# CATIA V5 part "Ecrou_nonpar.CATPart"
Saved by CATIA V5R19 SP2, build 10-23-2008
Part number: Ecrou
Bounding box of the stored display mesh (mm): x -5.196 to 5.196, y -4.5 to 4.5, z -2 to 2
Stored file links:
  F:\Projet CAO\pièces et assemblages\mécanisme 577\577-SaintAime\577-SaintAime\Ecrou_nonpar.CATPart
  C:\Program Files\Dassault Systemes\B19\win_b64\reffiles\standard\MetricThickPitch.txt
  C:\Program Files\Dassault Systemes\B19\win_b64\reffiles\standard\MetricThinPitch.txt
  C:\Users\Tilou\Documents\Cours M1\Conception\conception fauroux\Projet CAO\pièces et assemblages\mécanisme 577\mecanisme 577.CATProduct
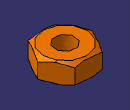
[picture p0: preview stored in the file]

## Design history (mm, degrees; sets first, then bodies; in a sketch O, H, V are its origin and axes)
Body1 (main body)
  Sketch1 on xy-plane, origin (0, 0, 0), H (1, 0, 0), V (0, 1, 0)
    point P1 (5.1962, 0)
    point P2 (2.5981, 4.5)
    point P3 (-2.5981, 4.5)
    point P4 (-5.1962, 0)
    point P5 (-2.5981, -4.5)
    point P6 (2.5981, -4.5)
    point P7 (3.8971, 2.25)
    line L1 (5.1962, 0) -> (2.5981, 4.5)
    line L2 (2.5981, 4.5) -> (-2.5981, 4.5)
    line L3 (-2.5981, 4.5) -> (-5.1962, 0)
    line L4 (-5.1962, 0) -> (-2.5981, -4.5)
    line L5 (-2.5981, -4.5) -> (2.5981, -4.5)
    line L6 (2.5981, -4.5) -> (5.1962, 0)
    construction line L7 (0, 0) -> (3.8971, 2.25)
    construction circle A1 centre (0, 0) radius 5.1962
    construction arc A2 centre (-2.5981, -4.5) radius 5.1962 from (-5.1962, 0) to (2.5981, -4.5) cw
    construction arc A3 centre (2.5981, 4.5) radius 5.1962 from (-2.5981, 4.5) to (5.1962, 0) ccw
    axis line L8 (-26.2747, 0) -> (18.9581, 0)
    distance L2 L5 = 9
    coincidence: A1 P1, A1 P2, A1 P3, A1 P4, A1 P5, A1 P6, A2 O, A3 O, L8 P1, P4 L8
    midpoint: P7 L1
    parallelism: L1 L4
    horizontal: L8 H
  Pad1: profile Sketch1, direction (0, 0, 1), length 2, mirrored extent
  Body2
    Sketch2 on zx-plane, origin (0, 0, 0), H (-1, 0, 0), V (0, 0, 1)
      line L1 (4.1962, 2) -> (5.1962, 2)
      line L2 (5.1962, 2) -> (5.1962, 1.4226)
      line L3 (5.1962, 1.4226) -> (4.1962, 2)
      reference projected line E1 (5.1962, -4.2) -> (5.1962, 4.2) from edge [face of Pad1 from Sketch1.L4 | face of Pad1 from Sketch1.L3]
      reference projected line E2 (4.6188, 2) -> (9.2376, 2) from edge [face of Pad1 from Sketch1.L3 | end face of Pad1]
      angle L3 L1 = 30
      length L1 = 1
      horizontal: L1 H
      vertical: L2 V
      coincidence: L2 E1, L1 E2
    Shaft1: profile Sketch2, axis Sketch2.V, angle 360
    Mirror1: of Shaft1, Sketch2, about xy-plane
  Remove1: tool Body2
  Sketch3 on end face of Pad1, origin (1.9425, -2.7682, 2), H (1, 0, 0), V (0, 1, 0)
    point P1 (-1.9425, 2.7682)
  Hole1: placed by Sketch3, at (0, 0, 2) direction (0, 0, -1), diameter 4, depth 10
